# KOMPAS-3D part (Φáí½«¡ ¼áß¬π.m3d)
File: created 06.04.2016 12:01:11, last saved 22.07.2016 15:32:27.
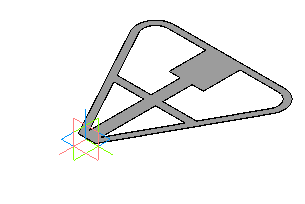
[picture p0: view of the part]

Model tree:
1. Эскиз:1
2. Операция выдавливания:1
     Толщина стенки 2 = 15; Расстояние 1 = 0.6; Расстояние 2 = 96.2519
3. Эскиз:2
4. Операция выдавливания:2
     Толщина стенки 1 = 12; Толщина стенки 2 = 12; Расстояние 1 = 0.6; Расстояние 2 = 0.6
5. Эскиз:3
6. Операция выдавливания:3
     Толщина стенки 1 = 35; Толщина стенки 2 = 35; Расстояние 1 = 0.6; Расстояние 2 = 0.6
7. Эскиз:4
8. Операция выдавливания:4
     Толщина стенки 1 = 15; Толщина стенки 2 = 30; Расстояние 1 = 0.6; Расстояние 2 = 0.6
9. Эскиз:5
10. Вырезать элемент выдавливания:1
     Толщина стенки 1 = 2; Толщина стенки 2 = 2; Расстояние 1 = 10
